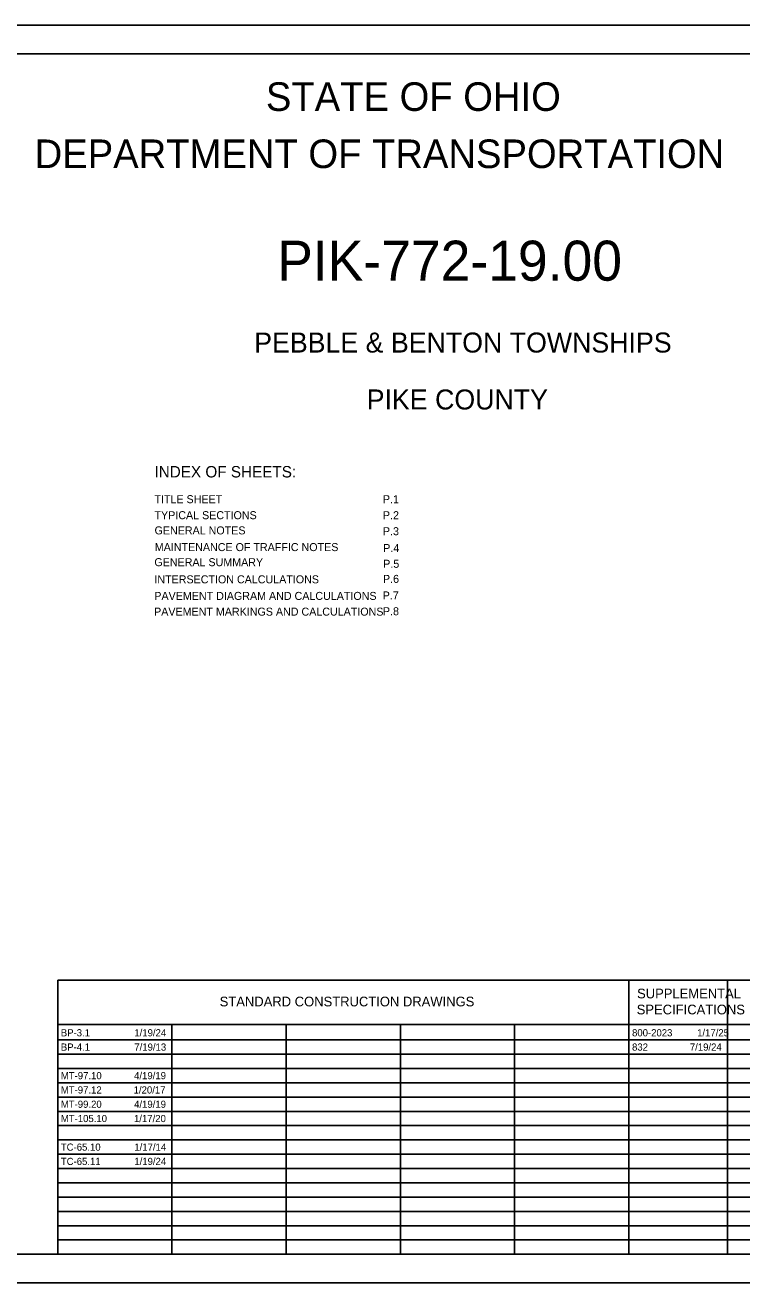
# Model space of a CAD drawing. Extents: x 0 to 34, y 0 to 22.
# Drawn here: x 9.58 to 22.13, y 0 to 22 of the extents above; entities that cross this region are included whole.
import ezdxf

# ---------------------------------------------------------------- set-up
doc = ezdxf.new("R2010")
doc.units = 0
for name, color, linetype in [('Default', 7, 'Continuous'), ('SH_Border', 7, 'Continuous'), ('SH_Cut_Line', 7, 'Continuous'), ('SH_Data', 7, 'Continuous'), ('SH_Text', 7, 'Continuous')]:
    doc.layers.add(name, color=color, linetype=linetype)

msp = doc.modelspace()

# ---------------------------------------------------------------- linework, layer by layer
at = {"layer": 'SH_Border'}
msp.add_lwpolyline([(1.5, 21.5), (33.5, 21.5), (33.5, 0.5), (1.5, 0.5)], close=True, dxfattribs=at)
at = {"layer": 'SH_Cut_Line'}
msp.add_lwpolyline([(0, 0), (34, 0), (34, 22), (0, 22)], close=True, dxfattribs=at)
at = {"layer": 'SH_Data'}
for p, q in [((10.15, 5.292), (23.6, 5.292)), ((10.15, 0.5), (10.15, 5.292)), ((20.15, 0.5), (20.15, 5.292)), ((21.875, 0.5), (21.875, 5.292)), ((10.15, 4.521), (23.6, 4.521)), ((12.15, 0.5), (12.15, 4.521)), ((14.15, 0.5), (14.15, 4.521)), ((16.15, 0.5), (16.15, 4.521)), ((18.15, 0.5), (18.15, 4.521)), ((10.15, 4.25), (23.6, 4.25)), ((10.15, 4), (23.6, 4)), ((10.15, 3.75), (23.6, 3.75)), ((10.15, 3.5), (23.6, 3.5)), ((10.15, 3.25), (23.6, 3.25)), ((10.15, 3), (23.6, 3)), ((10.15, 2.75), (23.6, 2.75)), ((10.15, 2.5), (23.6, 2.5)), ((10.15, 2.25), (23.6, 2.25)), ((10.15, 2), (23.6, 2)), ((10.15, 1.75), (23.6, 1.75)), ((10.15, 1.5), (23.6, 1.5)), ((10.15, 1.25), (23.6, 1.25)), ((10.15, 1), (23.6, 1)), ((10.15, 0.75), (23.6, 0.75))]:
    msp.add_line(p, q, dxfattribs=at)

# ---------------------------------------------------------------- texts
at = {"layer": 'Default'}
for s, height, p in [('PIK-772-19.00', 0.7, (13.993, 17.53)), ('PEBBLE & BENTON TOWNSHIPS', 0.35, (13.59, 16.273)), ('PIKE COUNTY', 0.35, (15.56, 15.277)), ('TITLE SHEET', 0.14, (11.844, 13.638)), ('P.1', 0.14, (15.844, 13.638)), ('TYPICAL SECTIONS', 0.14, (11.845, 13.358)), ('P.2', 0.14, (15.844, 13.358)), ('GENERAL NOTES', 0.14, (11.846, 13.092)), ('P.3', 0.14, (15.844, 13.078)), ('MAINTENANCE OF TRAFFIC NOTES', 0.14, (11.85, 12.8)), ('P.4', 0.14, (15.849, 12.783)), ('GENERAL SUMMARY', 0.14, (11.843, 12.536)), ('P.5', 0.14, (15.849, 12.508)), ('INTERSECTION CALCULATIONS', 0.14, (11.843, 12.236)), ('P.6', 0.14, (15.845, 12.244)), ('PAVEMENT DIAGRAM AND CALCULATIONS', 0.14, (11.842, 11.946)), ('P.7', 0.14, (15.84, 11.954)), ('PAVEMENT MARKINGS AND CALCULATIONS', 0.14, (11.838, 11.671)), ('P.8', 0.14, (15.844, 11.678)), ('BP-3.1', 0.125, (10.205, 4.312)), ('1/19/24', 0.125, (11.492, 4.312)), ('800-2023', 0.125, (20.205, 4.312)), ('1/17/25', 0.125, (21.344, 4.312)), ('BP-4.1', 0.125, (10.205, 4.062)), ('7/19/13', 0.125, (11.492, 4.062)), ('832', 0.125, (20.205, 4.062)), ('7/19/24', 0.125, (21.217, 4.062)), ('MT-97.10', 0.125, (10.205, 3.562)), ('4/19/19', 0.125, (11.488, 3.562)), ('MT-97.12', 0.125, (10.205, 3.312)), ('1/20/17', 0.125, (11.48, 3.312)), ('MT-99.20', 0.125, (10.205, 3.062)), ('4/19/19', 0.125, (11.488, 3.062)), ('MT-105.10', 0.125, (10.205, 2.812)), ('1/17/20', 0.125, (11.486, 2.812)), ('TC-65.10', 0.125, (10.205, 2.312)), ('1/17/14', 0.125, (11.492, 2.312)), ('TC-65.11', 0.125, (10.205, 2.062)), ('1/19/24', 0.125, (11.492, 2.062))]:
    msp.add_text(s, height=height, dxfattribs=at).set_placement(p)
at = {"layer": 'SH_Text'}
for s, height, p in [('STATE OF OHIO', 0.5, (13.795, 20.5)), ('DEPARTMENT OF TRANSPORTATION', 0.5, (9.747, 19.5)), ('INDEX OF SHEETS:', 0.2, (11.844, 14.088)), ('SUPPLEMENTAL', 0.17, (20.293, 4.976)), ('STANDARD CONSTRUCTION DRAWINGS', 0.17, (12.986, 4.836)), ('SPECIFICATIONS', 0.17, (20.287, 4.696))]:
    msp.add_text(s, height=height, dxfattribs=at).set_placement(p)

doc.saveas('drawing.dxf')
